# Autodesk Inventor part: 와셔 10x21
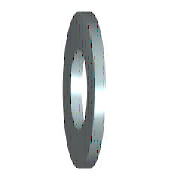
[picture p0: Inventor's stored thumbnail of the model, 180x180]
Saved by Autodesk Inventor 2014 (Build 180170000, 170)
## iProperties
Created: 2012-02
Part Number: 와셔 10x21
Material: 강철, 연강
Description: 평면 와셔
Document SubType Name: Modeling
Standard: KS B 1326
Designer: mduedu
Standards Organization: KS
Language: ko-KR
Size Designation: 10x21
Categories: <MemberInstance><Categories><Category DisplayName="조임쇠" InternalName="e4da775c-781d-43d5-af7c-5136215cf5a6" Mnemonic="FSTN"><Category DisplayName="와셔" InternalN
Density: 1 g/cm^3
Appearance: Blue - Wall Paint - Glossy
IsCustomPart: 1
Author: mduedu
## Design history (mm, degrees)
sketch "스케치"
  geometry: C1 r 10.5 at (0, 0); C2 r 5.25 at (0, 0); 1 further point
  constraints: 2 centre point, 2 coincident
  dimensions: "d0" = 10.5 diameter of C2 (= SD1); "d1" = 21 diameter of C1 (= SD2)
extrude "본체" new body sketch "스케치" distance "d2" = 2 (= SD); taper "d3" = 0 deg
workaxis "Work Axis1"
workplane "Work Plane1"
body "Solid1"
other parameters: "SD1" = 10.5 [user parameter; used in 1 equation term], "SD2" = 21 [user parameter; used in 1 equation term], "SD" = 2 [user parameter; used in 1 equation term], "d4" = 0, "d5" = 0, "d6" = 0, "d7" = 0
